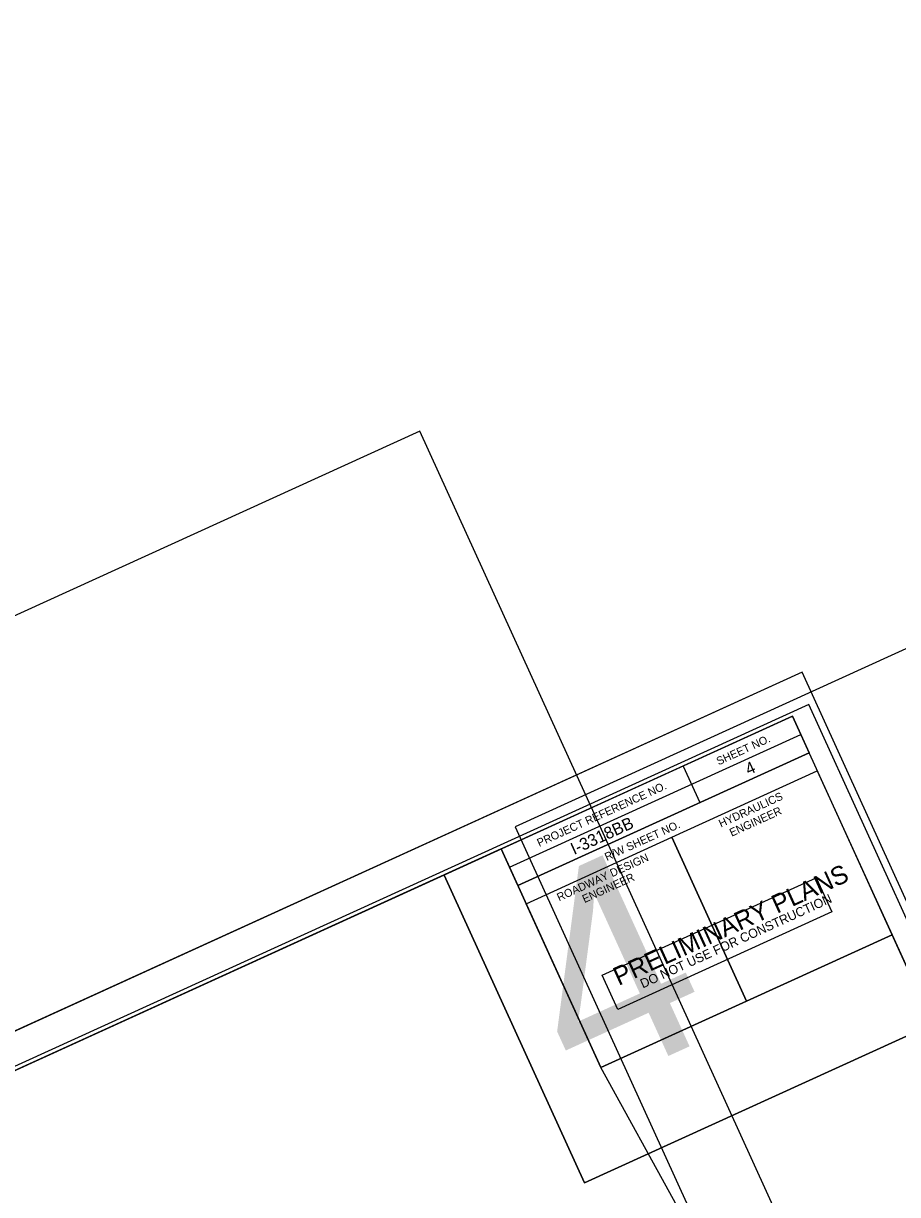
# Model space of a CAD drawing. Extents: x 2246788 to 2250969, y 662010 to 664598.
# Drawn here: x 2247833 to 2248379, y 663378 to 664110 of the extents above; entities that cross this region are included whole.
import ezdxf

# ---------------------------------------------------------------- set-up
doc = ezdxf.new("R2010")
doc.units = 0
for name, color, linetype in [('Sheet Clip Boundary CELL', 7, 'Continuous'), ('Sheet Cutting Line CELL', 7, 'Continuous'), ('Sheet Data Field CELL', 7, 'Continuous'), ('Sheet Layout Plan Border', 7, 'Continuous'), ('Sheet Plan CELL', 7, 'Continuous'), ('Sheet Plan Layout CELL', 7, 'Continuous'), ('Sheet Plot Border Inside CELL', 7, 'Continuous'), ('Sheet Plot Border Outside CELL', 7, 'Continuous'), ('Sheet Sticker Preliminary CELL', 7, 'Continuous')]:
    doc.layers.add(name, color=color, linetype=linetype)

msp = doc.modelspace()

# ---------------------------------------------------------------- linework, layer by layer
at = {"layer": 'Sheet Clip Boundary CELL'}
msp.add_lwpolyline([(2248573.04, 662641.59), (2248489.82, 662824.78), (2248241.67, 663371.06), (2248193.86, 663457.79), (2248131.62, 663594.34), (2247008.72, 663082.61), (2247444.44, 662127.31)], close=True, dxfattribs=at)
at = {"layer": 'Sheet Cutting Line CELL'}
msp.add_line((2248319.81, 663704.79), (2246787.87, 663006.71), dxfattribs=at)
at = {"layer": 'Sheet Layout Plan Border'}
for points in [[(2248198.13, 663481.51), (2248575.77, 662652.77), (2249849.75, 663233.3), (2249502.05, 663996.33), (2249329.83, 663917.85), (2249242.13, 664110.3), (2248140.38, 663608.25)], [(2248661.41, 662581.57), (2248242.84, 663500.12), (2248080.88, 663855.55), (2247317.85, 663507.85), (2247396.33, 663335.63), (2247203.88, 663247.93), (2247705.93, 662146.18)]]:
    msp.add_lwpolyline(points, close=True, dxfattribs=at)
at = {"layer": 'Sheet Plan CELL'}
for p, q in [((2248136.81, 663582.91), (2248318.86, 663665.85)), ((2248142.02, 663571.51), (2248324.04, 663654.48)), ((2248142.02, 663571.51), (2248324.04, 663654.48)), ((2248245.41, 663646.11), (2248255.82, 663623.38)), ((2248238.24, 663601.63), (2248284.89, 663499.3)), ((2248142.02, 663571.51), (2248147.2, 663560.15))]:
    msp.add_line(p, q, dxfattribs=at)
for points in [[(2248313.69, 663677.29), (2246948.69, 663055.28), (2247384.08, 662099.81), (2248749.06, 662721.8)], [(2248131.62, 663594.34), (2248313.69, 663677.29), (2248324.04, 663654.48), (2248142.02, 663571.51)], [(2248238.24, 663601.63), (2248329.22, 663643.1), (2248375.89, 663540.73), (2248284.9, 663499.25)], [(2248147.2, 663560.15), (2248238.24, 663601.63), (2248284.9, 663499.25), (2248193.86, 663457.79)], [(2247384.08, 662099.81), (2246948.68, 663055.25), (2248131.62, 663594.34), (2248193.86, 663457.79), (2248375.89, 663540.73), (2248749.06, 662721.8)]]:
    msp.add_lwpolyline(points, close=True, dxfattribs=at)
at = {"layer": 'Sheet Plan Layout CELL'}
for points in [[(2248183.64, 663385.62), (2248401.37, 663484.84), (2248313.7, 663677.29), (2248095.94, 663578.07)], [(2246948.68, 663055.25), (2247384.08, 662099.81), (2248749.05, 662721.8), (2248401.35, 663484.83), (2248183.64, 663385.62), (2248095.94, 663578.07)]]:
    msp.add_lwpolyline(points, close=True, dxfattribs=at)
at = {"layer": 'Sheet Plot Border Inside CELL'}
msp.add_lwpolyline([(2247245.45, 662033.88), (2248761.46, 662724.71), (2248324.01, 663684.73), (2246807.99, 662993.9)], close=True, dxfattribs=at)
at = {"layer": 'Sheet Plot Border Outside CELL'}
msp.add_lwpolyline([(2247241.92, 662010.29), (2248773.86, 662708.37), (2248319.81, 663704.79), (2246787.87, 663006.71)], close=True, dxfattribs=at)
at = {"layer": 'Sheet Sticker Preliminary CELL'}
msp.add_lwpolyline([(2248204.57, 663494.04), (2248194.82, 663515.43), (2248328.59, 663576.38), (2248338.33, 663555)], close=True, dxfattribs=at)

# ---------------------------------------------------------------- texts
at = {"layer": 'Sheet Data Field CELL'}
for s, p in [('4', (2248286.28, 663640.35)), ('I-3318BB', (2248177.16, 663590.56))]:
    msp.add_text(s, height=7.5, rotation=24.49795, dxfattribs=at).set_placement(p)
at = {"layer": 'Sheet Plan CELL'}
for s, height, p in [('SHEET NO.', 5, (2248267.56, 663646.57)), ('PROJECT REFERENCE NO.', 5.0001, (2248155.44, 663595.6)), ('HYDRAULICS', 5, (2248268.98, 663607.64)), ('ENGINEER', 5, (2248275.71, 663601.96)), ('R/W SHEET NO.', 5.0001, (2248197.7, 663586.78)), ('ROADWAY DESIGN', 5.0001, (2248167.86, 663561.54)), ('ENGINEER', 5, (2248183.71, 663560.48))]:
    msp.add_text(s, height=height, rotation=24.49795, dxfattribs=at).set_placement(p)
at = {"layer": 'Sheet Plan Layout CELL'}
msp.add_text('4 ', height=131.25, rotation=24.49794, dxfattribs=at).set_placement((2248180.68, 663439.67))
at = {"layer": 'Sheet Sticker Preliminary CELL'}
for s, height, p in [('PRELIMINARY PLANS', 11.52, (2248205.03, 663508.7)), ('DO NOT USE FOR CONSTRUCTION', 5.76, (2248220.14, 663507.13))]:
    msp.add_text(s, height=height, rotation=24.49794, dxfattribs=at).set_placement(p)

doc.saveas('drawing.dxf')
